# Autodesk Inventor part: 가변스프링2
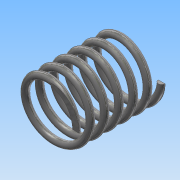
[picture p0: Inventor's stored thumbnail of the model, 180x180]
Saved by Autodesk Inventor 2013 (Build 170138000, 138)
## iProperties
Created: 2019-07
Part Number: 가변스프링2
Material: 강철, 탄소
Document SubType Name: Modeling
Designer: Administrator
Density: 7.87 g/cm^3
Mass: 7.78998 g
Surface Area: 20.0702 cm^2
Volume: 0.989832 cm^3
Author: Administrator
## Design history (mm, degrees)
sketch "스케치1"
  geometry: L1 (0, 0)-(0, 25.33); L2 (0, 25.33)-(16.881, 25.33); C1 r 1 at (8.5, 0)
  constraints: 4 end point, 1 centre point, 1 horizontal alignment, 1 perpendicular, 1 vertical
  dimensions: "d0" = 25.33013 distance of L1.start L1.end (derived); "d1" = 2 diameter of C1; "d2" = 17 diameter of C1.centre L1
feature "코일1" sketch "스케치1" pitch "d3" = 10; turns "d5" = 6; dims "d4" = 25.33013 (= d0), "d6" = 0, angle "d7" = 90 deg, angle "d8" = 90 deg, "d9" = 0, "d10" = 0
sketch "스케치2"
  geometry: L1 (0, 12.5)-(25.33, 12.5); L2 (25.33, 12.5)-(25.33, -12.5); L3 (25.33, -12.5)-(0, -12.5); L4 (0, -12.5)-(0, 12.5); 2 further points
  constraints: 8 end point, 2 parallel, 1 coincident, 1 horizontal, 1 midpoint, 1 perpendicular
  dimensions: "d11" = 25.33013 distance between parallel lines of L2 L4 (derived); "d13" = 25 distance between parallel lines of L1 L3
extrude "돌출1" sketch "스케치2" stored distance "d14" = 50; taper "d15" = 0 deg
node "솔리드1"
